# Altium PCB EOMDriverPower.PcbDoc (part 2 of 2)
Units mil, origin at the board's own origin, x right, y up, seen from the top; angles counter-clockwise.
Board outline 6400 x 9100 mil, 6 copper layers (Top Layer, GND1, PWR1, PWR2, GND2, Bottom Layer); 300 components, 184 nets, 876 pads, 174 vias.
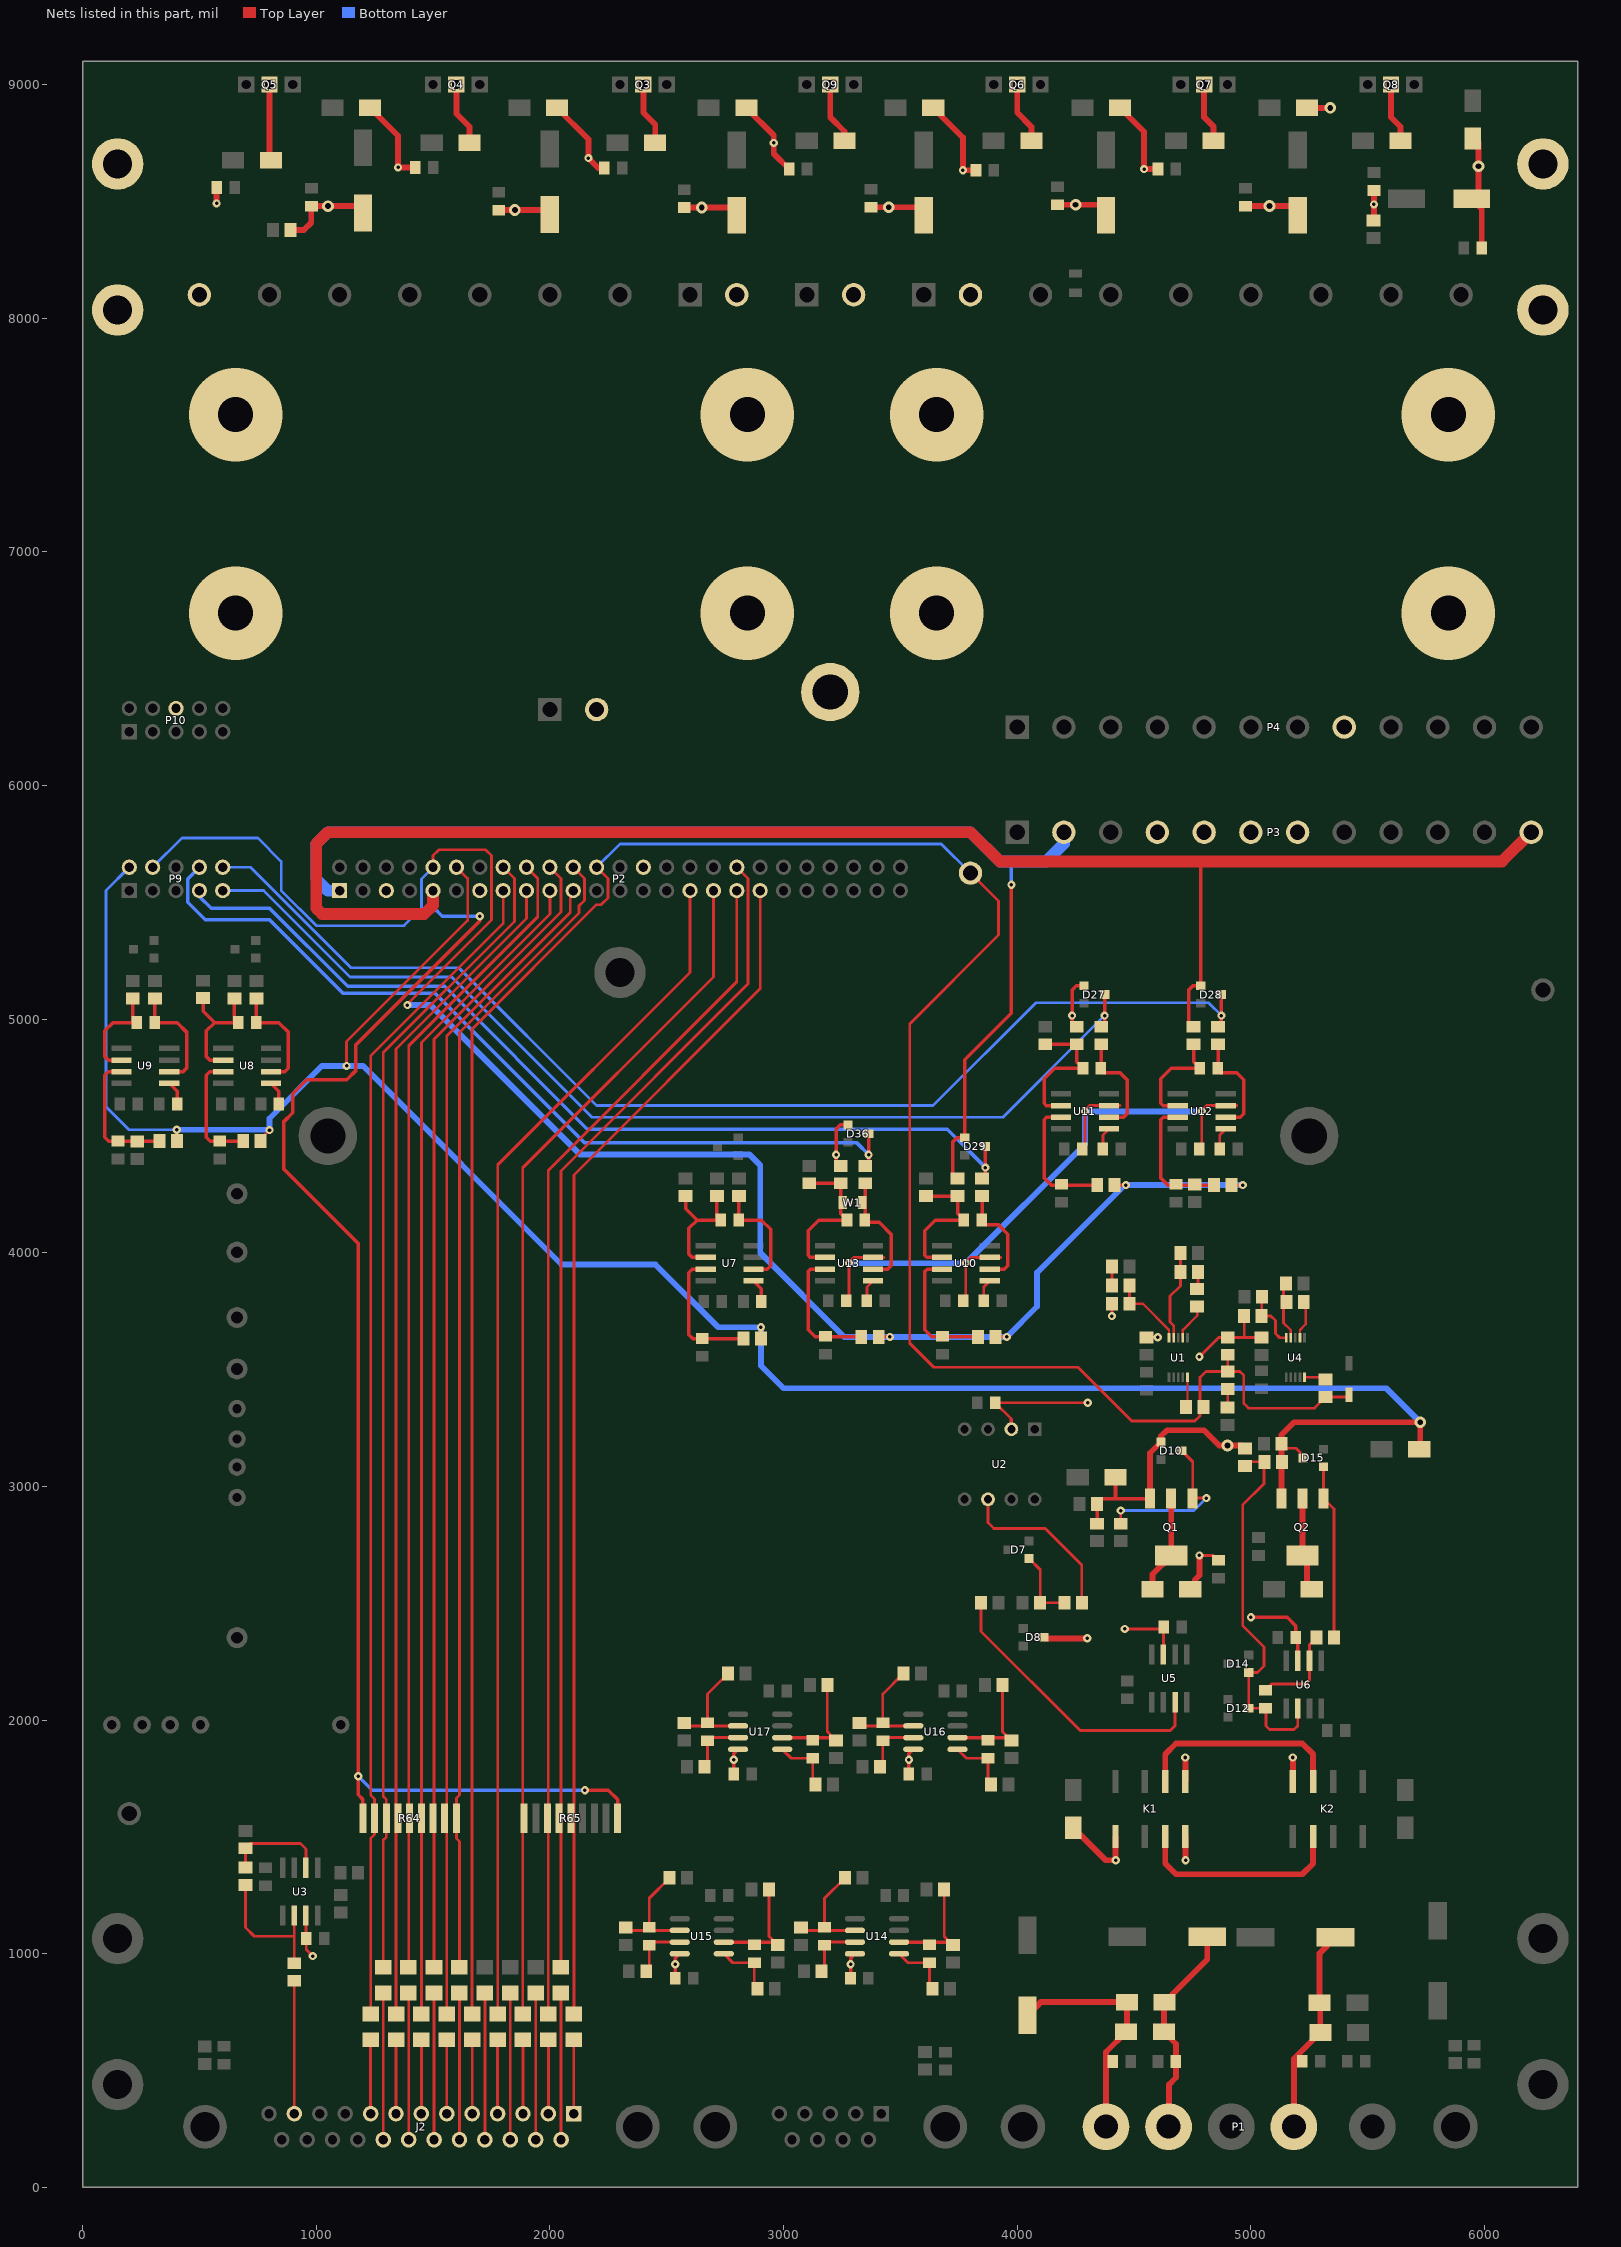
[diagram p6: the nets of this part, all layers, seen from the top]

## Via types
v1: diameter 35, hole 15, Top Layer to Bottom Layer, 147 vias
v2: diameter 50, hole 25, Top Layer to Bottom Layer, 19 vias
v3: diameter 280/400 (per signal layer), hole 150, Top Layer to Bottom Layer, 8 vias

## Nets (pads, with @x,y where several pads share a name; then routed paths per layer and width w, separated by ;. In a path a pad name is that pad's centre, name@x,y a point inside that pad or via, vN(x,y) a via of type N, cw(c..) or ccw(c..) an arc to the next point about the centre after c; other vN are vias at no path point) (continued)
NetC24_1: C24.1 R32.2 U6.6 | length 399.9
  Top Layer w12: C24.1@5063,2128.39 5089.61,2155 5235,2155 5251,2171 U6.6@5251,2254.36 5251,2323.4 R32.2@5280.6,2353
NetC24_2: C24.2 D12.3 D14.1 R29.2 R31.1 U6.2 | length 1640.3
  Top Layer w12: R29.2@4975,3087.6 4993,3105.6 5056.6,3105.6 5056.6,3011.6 4965,2920 4965,2405 5056.6,2313.4 5056.6,2231.6 5028.6,2203.6 D14.1@4991.29,2203.6 D12.3@4991.29,2051 5062.39,2051 C24.2@5063,2051.61 5065,2049.61 5065,1975 5080,1960 5185,1960 5201,1976 U6.2@5201,2049.64
NetC26_2: C26.2 R34.2 U7.3 | length 583.5
  Top Layer w15: U7.3@2666.64,3930 2610,3930 2595,3915 2595,3650 2612,3633 R34.2@2828.6,3633
NetC27_2: C27.2 R35.2 U8.3 | length 507.5
  Top Layer w15: U8.3@601.64,4775 545,4775 530,4760 530,4495 547,4478 R35.2@687.6,4478
NetC28_2: C28.2 R36.2 R39.1 U9.3 | length 583.5
  Top Layer w15: U9.3@166.64,4775 110,4775 95,4760 95,4495 112,4478 R36.2@328.6,4478
NetC32_2: C32.2 U7.5 | length 102.1
  Top Layer w15: U7.5@2871.36,3880 2905.39,3845.98 C32.2@2905.39,3792
NetC33_2: C33.2 U8.5 | length 102.1
  Top Layer w15: U8.5@806.36,4725 840.39,4690.98 C33.2@840.39,4637
NetC34_2: C34.2 U9.5 | length 102.1
  Top Layer w15: U9.5@371.36,4725 405.39,4690.98 C34.2@405.39,4637
NetC35_1: C35.1 R41.2 U7.6 | length 489
  Top Layer w15: R41.2@2808.39,4240.98 C35.1@2808.39,4140 2905,4140 2945,4100 2945,3945 2930,3930 U7.6@2871.36,3930
NetC35_2: C35.2 R37.2 R40.2 U7.2 | length 568.5
  Top Layer w15: R37.2@2581,4243.6 2581,4189 2630,4140 ; U7.2@2666.64,3980 2610,3980 2595,3995 2595,4105 2630,4140 ; R40.2@2715,4243.6 2715,4145 C35.2@2710,4140 ; C35.2@2731.61,4140 C35.2@2710,4140 ; 2630,4140 C35.2@2710,4140
NetC36_1: C36.1 R43.2 U8.6 | length 489
  Top Layer w15: R43.2@743.39,5085.98 C36.1@743.39,4985 840,4985 880,4945 880,4790 865,4775 U8.6@806.36,4775
NetC36_2: C36.2 R38.2 R42.2 U8.2 | length 569.5
  Top Layer w15: R38.2@516,5089.6 516,5034 565,4985 ; U8.2@601.64,4825 545,4825 530,4840 530,4950 565,4985 ; R42.2@650,5088.6 650,4990 C36.2@645,4985 ; C36.2@666.61,4985 C36.2@645,4985 ; 565,4985 C36.2@645,4985
NetC37_1: C37.1 R45.2 U9.6 | length 489
  Top Layer w15: R45.2@308.39,5085.98 C37.1@308.39,4985 405,4985 445,4945 445,4790 430,4775 U9.6@371.36,4775
NetC37_2: C37.2 R44.2 U9.2 | length 444.6
  Top Layer w15: U9.2@166.64,4825 110,4825 95,4840 95,4950 130,4985 C37.2@210,4985 ; R44.2@215,5088.6 215,4990 C37.2@210,4985 ; C37.2@231.61,4985 C37.2@210,4985
NetC41_1: C41.1 R47.2 U10.3 | length 566.8
  Top Layer w15: U10.3@3677.64,3930 3615,3930 3605,3920 3605,3670 3635,3640 R47.2@3832.6,3640
NetC42_1: C42.1 R48.2 U11.3 | length 566.8
  Top Layer w15: U11.3@4187.64,4580 4125,4580 4115,4570 4115,4320 4145,4290 R48.2@4342.6,4290
NetC43_1: C43.1 R49.2 R52.1 U12.3 | length 566.8
  Top Layer w15: U12.3@4687.64,4580 4625,4580 4615,4570 4615,4320 4645,4290 R49.2@4842.6,4290
NetC47_1: C47.1 U10.5 | length 100.7
  Top Layer w12: C47.1@3856.61,3790 3856.61,3854.25 U10.5@3882.36,3880
NetC48_1: C48.1 U11.5 | length 100.7
  Top Layer w12: C48.1@4366.61,4440 4366.61,4504.25 U11.5@4392.36,4530
NetC49_1: C49.1 U12.5 | length 100.7
  Top Layer w12: C49.1@4866.61,4440 4866.61,4504.25 U12.5@4892.36,4530
NetC50_1: C50.1 R50.2 R54.1 U10.2 | length 615.7
  Top Layer w15: R50.2@3610,4242.6 R54.1@3745,4242.6 3745,4166.61 C50.1@3771.61,4140 3650,4140 3605,4095 3605,3990 3615,3980 U10.2@3677.64,3980
NetC50_2: C50.2 R53.1 U10.6 | length 456.3
  Top Layer w15: R53.1@3850,4242.6 3850,4140 3870,4120 3920,4120 3960,4080 3960,3945 3945,3930 U10.6@3882.36,3930
NetC51_1: C51.1 R51.2 R56.1 U11.2 | length 615.7
  Top Layer w15: R51.2@4120,4892.6 R56.1@4255,4892.6 4255,4816.61 C51.1@4281.61,4790 4160,4790 4115,4745 4115,4640 4125,4630 U11.2@4187.64,4630
NetC51_2: C51.2 R55.1 U11.6 | length 468
  Top Layer w15: R55.1@4360,4892.6 4360,4780 4370,4770 4440,4770 4470,4740 4470,4595 4455,4580 U11.6@4392.36,4580
NetC52_1: C52.1 R58.1 U12.2 | length 480.7
  Top Layer w15: U12.2@4687.64,4630 4625,4630 4615,4640 4615,4745 4660,4790 C52.1@4781.61,4790 4755,4816.61 R58.1@4755,4892.6
NetC52_2: C52.2 R57.1 U12.6 | length 468
  Top Layer w15: R57.1@4860,4892.6 4860,4780 4870,4770 4940,4770 4970,4740 4970,4595 4955,4580 U12.6@4892.36,4580
NetC56_1: C56.1 R60.2 U13.3 | length 566.8
  Top Layer w15: U13.3@3177.64,3930 3115,3930 3105,3920 3105,3670 3135,3640 R60.2@3332.6,3640
NetC62_1: C62.1 U13.5 | length 100.7
  Top Layer w12: C62.1@3356.61,3790 3356.61,3854.25 U13.5@3382.36,3880
NetC63_1: C63.1 R61.2 R63.1 U13.2 W1.1 | length 712
  Top Layer w8: W1.1@3253.66,4215 W1.1@3295,4215
  Top Layer w15: R61.2@3110,4297.6 R63.1@3245,4297.6 3245,4166.61 C63.1@3271.61,4140 3150,4140 3105,4095 3105,3990 3115,3980 U13.2@3177.64,3980
NetC63_2: C63.2 R62.1 U13.6 W1.2 | length 505.4
  Top Layer w15: R62.1@3350,4297.6 3350,4150 3370,4130 3410,4130 3460,4080 3460,3945 3445,3930 U13.6@3382.36,3930
NetC79_1: C79.1 R72.2 U14.7 | length 252.9
  Top Layer w12: R72.2@3162.4,925 3175,937.6 C79.1@3175,1036.61 3188.39,1050 U14.7@3305.51,1050
NetC79_2: C79.2 R67.1 R73.2 U14.6 | length 483.5
  Top Layer w12: R73.2@3075,1112.4 3087.4,1100 U14.6@3305.51,1100 ; C79.2@3175,1113.39 3175,1237.4 R67.1@3262.6,1325
NetC80_1: C80.1 R76.2 U15.7 | length 252.9
  Top Layer w12: R76.2@2412.4,925 2425,937.6 C80.1@2425,1036.61 2438.39,1050 U15.7@2555.51,1050
NetC80_2: C80.2 R69.1 R77.2 U15.6 | length 483.5
  Top Layer w12: R77.2@2325,1112.4 2337.4,1100 U15.6@2555.51,1100 ; C80.2@2425,1113.39 2425,1237.4 R69.1@2512.6,1325
NetC81_1: C81.1 R71.2 U14.1 | length 263.2
  Top Layer w12: U14.1@3494.49,1000 3532.87,961.61 C81.1@3625,961.61 3625,862.6 R71.2@3637.6,850
NetC81_2: C81.2 R66.1 R70.2 U14.2 | length 471.1
  Top Layer w12: R66.1@3687.4,1275 3687.4,1075 3712.4,1050 R70.2@3725,1037.4
  Top Layer w15: U14.2@3494.49,1050 R70.2@3712.4,1050
NetC82_1: C82.1 R75.2 U15.1 | length 263.2
  Top Layer w12: U15.1@2744.49,1000 2782.87,961.61 C82.1@2875,961.61 2875,862.6 R75.2@2887.6,850
NetC82_2: C82.2 R68.1 R74.2 U15.2 | length 471.1
  Top Layer w12: R68.1@2937.4,1275 2937.4,1075 2962.4,1050 R74.2@2975,1037.4
  Top Layer w15: U15.2@2744.49,1050 R74.2@2962.4,1050
NetC87_1: C87.1 R84.2 U16.7 | length 252.9
  Top Layer w12: R84.2@3412.4,1800 3425,1812.6 C87.1@3425,1911.61 3438.39,1925 U16.7@3555.51,1925
NetC87_2: C87.2 R79.1 R85.2 U16.6 | length 483.5
  Top Layer w12: R85.2@3325,1987.4 3337.4,1975 U16.6@3555.51,1975 ; C87.2@3425,1988.39 3425,2112.4 R79.1@3512.6,2200
NetC88_1: C88.1 R88.2 U17.7 | length 252.9
  Top Layer w12: R88.2@2662.4,1800 2675,1812.6 C88.1@2675,1911.61 2688.39,1925 U17.7@2805.51,1925
NetC88_2: C88.2 R81.1 R89.2 U17.6 | length 483.5
  Top Layer w12: R89.2@2575,1987.4 2587.4,1975 U17.6@2805.51,1975 ; C88.2@2675,1988.39 2675,2112.4 R81.1@2762.6,2200
NetC89_1: C89.1 R83.2 U16.1 | length 263.2
  Top Layer w12: U16.1@3744.49,1875 3782.87,1836.61 C89.1@3875,1836.61 3875,1737.6 R83.2@3887.6,1725
NetC89_2: C89.2 R78.1 R82.2 U16.2 | length 471.1
  Top Layer w12: R78.1@3937.4,2150 3937.4,1950 3962.4,1925 R82.2@3975,1912.4
  Top Layer w15: U16.2@3744.49,1925 R82.2@3962.4,1925
NetC90_1: C90.1 R87.2 U17.1 | length 263.2
  Top Layer w12: U17.1@2994.49,1875 3032.87,1836.61 C90.1@3125,1836.61 3125,1737.6 R87.2@3137.6,1725
NetC90_2: C90.2 R80.1 R86.2 U17.2 | length 471.1
  Top Layer w12: R80.1@3187.4,2150 3187.4,1950 3212.4,1925 R86.2@3225,1912.4
  Top Layer w15: U17.2@2994.49,1925 R86.2@3212.4,1925
NetD7_1: D7.1 R18.2 R20.1 | length 312.7
  Top Layer w12: D7.1@4050.29,2691.6 4098.4,2643.49 R20.1@4098.4,2502 R18.2@4201.6,2502
NetD10_3: D10.3 Q1.1 R27.2 | length 726.6
  Top Layer w12: R27.2@4443,2840.4 v1(4443,2897) ; D10.3@4704.29,3153 4751.5,3105.79 4751.5,2950 v1(4810,2950)
  Bottom Layer w12: v1(4443,2897) 4757,2897 v1(4810,2950)
NetD11_2: D11.2 Q1.2 Q1.4 | length 421.1
  Top Layer w25: D11.2@4579.29,2560 4579.29,2624.24 Q1.4@4659,2703.95 Q1.2@4659,2948.05
NetD15_1: D15.1 Q2.1 R32.1 | length 749.9
  Top Layer w12: D15.1@5311.29,3084.6 5311.29,2948.31 Q2.1@5311.55,2948.05 5355.4,2904.2 R32.1@5355.4,2353
NetD17_1: D17.1 Q2.2 Q2.4 | length 404.5
  Top Layer w25: Q2.2@5221,2948.05 Q2.4@5221,2703.95 5240,2684.95 5240,2580.71 D17.1@5260.71,2560
NetD22_1: D22.1 Q3.2 | length 271
  Top Layer w25: Q3.2@2400,9000 2400,8880 2450.71,8829.29 D22.1@2450.71,8750
NetD23_1: D23.1 Q4.2 | length 273.1
  Top Layer w25: Q4.2@1600,9000 1600,8875 1655.71,8819.29 D23.1@1655.71,8750
NetD24_1: D24.1 Q5.2 | length 327.4
  Top Layer w25: Q5.2@800,9000 800,8680.71 D24.1@805.71,8675
NetD31_2: D31.2 Q6.2 | length 265.1
  Top Layer w25: Q6.2@4000,9000 4000,8880 4060.71,8819.29 D31.2@4060.71,8760
NetD32_2: D32.2 Q7.2 | length 256.9
  Top Layer w25: Q7.2@4800,9000 4800,8860 4840.71,8819.29 D32.2@4840.71,8760
NetD33_2: D33.2 Q8.2 | length 256.9
  Top Layer w25: Q8.2@5600,9000 5600,8860 5640.71,8819.29 D33.2@5640.71,8760
NetD37_2: D37.2 Q9.2 | length 265.1
  Top Layer w25: Q9.2@3200,9000 3200,8860 3260.71,8799.29 D37.2@3260.71,8760
NetFR1_2: FR1.2 J2.1 | length 315.6
  Top Layer w12: J2.1@2102.2,315.91 FR1.2@2102.2,631.48
NetFR2_2: FR2.2 J2.14 | length 627.8
  Top Layer w12: J2.14@2047.85,204.09 FR2.2@2047.85,831.88
NetFR3_2: FR3.2 J2.2 | length 315.6
  Top Layer w12: J2.2@1993.5,315.91 FR3.2@1993.5,631.48
NetFR4_2: FR4.2 J2.15 | length 627.8
  Top Layer w12: J2.15@1939.15,204.09 FR4.2@1939.15,831.88
NetFR5_2: FR5.2 J2.3 | length 315.6
  Top Layer w12: J2.3@1884.8,315.91 FR5.2@1884.8,631.48
NetFR6_2: FR6.2 J2.16 | length 627.8
  Top Layer w12: J2.16@1830.45,204.09 FR6.2@1830.45,831.88
NetFR7_2: FR7.2 J2.4 | length 315.6
  Top Layer w12: J2.4@1776.1,315.91 FR7.2@1776.1,631.48
NetFR8_2: FR8.2 J2.17 | length 627.8
  Top Layer w12: J2.17@1721.75,204.09 FR8.2@1721.75,831.88
NetFR9_2: FR9.2 J2.5 | length 315.6
  Top Layer w12: J2.5@1667.4,315.91 FR9.2@1667.4,631.48
NetFR10_2: FR10.2 J2.18 | length 627.8
  Top Layer w12: J2.18@1613.05,204.09 FR10.2@1613.05,831.88
NetFR11_2: FR11.2 J2.6 | length 315.6
  Top Layer w12: J2.6@1558.7,315.91 FR11.2@1558.7,631.48
NetFR12_2: FR12.2 J2.19 | length 627.8
  Top Layer w12: J2.19@1504.35,204.09 FR12.2@1504.35,831.88
NetFR13_2: FR13.2 J2.7 | length 315.6
  Top Layer w12: J2.7@1450,315.91 FR13.2@1450,631.48
NetFR14_2: FR14.2 J2.20 | length 627.8
  Top Layer w12: J2.20@1395.65,204.09 FR14.2@1395.65,831.88
NetFR15_2: FR15.2 J2.8 | length 315.6
  Top Layer w12: J2.8@1341.3,315.91 FR15.2@1341.3,631.48
NetFR16_2: FR16.2 J2.21 | length 627.8
  Top Layer w12: J2.21@1286.95,204.09 FR16.2@1286.95,831.88
NetFR17_2: FR17.2 J2.9 | length 316.1
  Top Layer w12: J2.9@1232.6,315.91 1232.6,631.48 FR17.2@1233,631.88
NetK1_1: K1.1 K2.4 | length 902.4
  Top Layer w25: K1.1@4633.39,1501.89 4633.39,1386.61 4680,1340 5220,1340 5266.61,1386.61 K2.4@5266.61,1501.89
NetK1_4: K1.4 K2.1 | length 902.4
  Top Layer w25: K1.4@4633.39,1738.11 4633.39,1853.39 4680,1900 5220,1900 5266.61,1853.39 K2.1@5266.61,1738.11
NetR4_2: R4.2 R6T.2 U1.10 | length 327.7
  Top Layer w10: R4.2@4480.4,3782 4538,3782 4650,3670 U1.10@4650,3636.29
  Top Layer w12: R4.2@4480.4,3782 R6T.2@4480.4,3860
NetR5_1: R5.1 R7T.2 U1.9 | length 388.4
  Top Layer w10: 4668.69,3689.31 4669.69,3688.31 U1.9@4669.69,3636.29
  Top Layer w12: 4668.69,3688.31 4668.69,3689.31 4654.34,3703.66 4654.34,3814.34 4698.6,3858.6 R7T.2@4698.6,3918 R5.1@4698.6,3999
NetR6_2: R6.2 R6T.1 | length 81
  Top Layer w12: R6T.1@4405.6,3860 R6.2@4405.6,3941
NetR7_1: R7.1 U1.7 | length 158.6
  Top Layer w10: U1.7@4709.06,3636.29 4709.06,3670.06 4770,3731 R7.1@4770,3769.6
NetR7_2: R7.2 R7T.1 | length 75
  Top Layer w12: R7.2@4770,3844.4 4773.4,3847.8 R7T.1@4773.4,3918
NetR10_2: R10.2 R15.1 U3.2 | length 441.2
  Top Layer w12: R15.1@697,1368.4 R10.2@697,1451.6 717.9,1472.5 932.5,1472.5 956,1449 U3.2@956,1368.36
NetR11_1: R11.1 U1.5 | length 129.5
  Top Layer w10: R11.1@4728.74,3346.14 U1.5@4728.74,3467
  Top Layer w11.5: R11.1@4722.6,3340 R11.1@4728.74,3346.14
NetR13_1: R13.1 R16.2 U4.10 | length 268.9
  Top Layer w10: 5123.71,3636.29 U4.10@5151,3636.29
  Top Layer w11: R13.1@5046.4,3730 R13.1@5057.29,3730
  Top Layer w12: R16.2@5047.4,3812 5046.4,3811 R13.1@5046.4,3730 5085,3730 5105,3710 5105,3655 5123.71,3636.29
NetR14_1: R14.1 R17.2 U4.9 | length 249.8
  Top Layer w10: 5140,3700 5170.69,3669.31 U4.9@5170.69,3636.29 ; R14.1@5140,3858.4 R14.1@5150.6,3869
  Top Layer w12: 5140,3700 R14.1@5140,3858.4
NetR15_2: R15.2 R19.2 U3.6 | length 609.6
  Top Layer w12: R15.2@697,1293.6 697,1113 735,1075 906,1075 ; R19.2@906,959.4 906,1075 ; U3.6@906,1163.64 906,1075
NetR17_1: R17.1 U4.7 | length 166.6
  Top Layer w10: U4.7@5210.06,3636.29 5210.06,3670.06 5235,3695
  Top Layer w12: R17.1@5226.4,3789 5235,3780.4 5235,3695
NetR18_1: R18.1 U2.6 | length 738.1
  Top Layer w12: U2.6@3875,2945 3875,2845 3900,2820 4120,2820 4276.4,2663.6 R18.1@4276.4,2502
NetR22_2: R22.2 U5.3 | length 1238.1
  Top Layer w12: R22.2@3845.6,2502 3845.6,2379.4 4270,1955 4655,1955 4676,1976 U5.3@4676,2076.64
NetR23_1: R23.1 U4.5 | length 94.2
  Top Layer w10: U4.5@5229.74,3467 5310.4,3467 R23.1@5320,3457.4
NetR25_1: R25.1 R26.2 | length 80.2
  Top Layer w12: R26.2@4901,3337.4 R25.1@4901,3417.6
NN18: C4.1 C9.2 D2.2 D4.2 K1.3 P1.4 | length 1002.3
  Top Layer w25: v1@4720,1400 K1.3@4720,1501.89 ; P1.4@5220,260 5185,295 5185,550.71 D2.2@5297.29,663 5297.29,787 D4.2@5294.29,790 5294.29,1002.03 C9.2@5362.26,1070
  other v1: 4720.79,1400
OK: D9.2 FR9.1 P2.24 R11.2 R23.2 R24.1 R25.2 TP8.1 | length 11525.8
  Top Layer w12: FR9.1@1667,742.12 1667,4957 2200,5490 2220,5490 2248.16,5518.16 2248.16,5601.84 P2.24@2200,5650 ; TP8.1@3800,5625 3920,5505 3920,5360 3540,4980 3540,3613.08 3643.08,3510 4260,3510 4490,3280 4760,3280 4782,3302 4782,3467 4807.4,3492.4 R25.2@4901,3492.4 ; R24.1@4901,3563.6 R25.2@4901,3492.4 ; D9.2@5420,3393.07 5409.53,3382.6 R23.2@5320,3382.6 5272.4,3335 4990,3335 4970,3355 4970,3475 4952.6,3492.4 R25.2@4901,3492.4
  Bottom Layer w12: P2.24@2200,5650 2300,5750 3675,5750 TP8.1@3800,5625
P5: D28.1 P2.9 P3.12 R58.2 R64.1 R65.1 | length 12914.8
  Top Layer w15: R64.1@1200,1580 1200,1660 1180,1680 v1(1180,1760) 1180,4040 860,4360 860,4560 900,4600 900,4680 960,4740 1130,4740 1170,4780 1170,4890 1700,5420 v1(1700,5440) ; v1(2150,1700) 2250,1700 2290,1660 R65.1@2290,1580 ; R58.2@4755,4967.4 4735,4987.4 4735,5125 4752.4,5142.4 D28.1@4785.71,5142.4 4785.71,5664.29 4775,5675
  Top Layer w50: P2.9@1500,5550 1500,5487.5 1462.5,5450 1025,5450 1000,5475 1000,5750 1050,5800 3800,5800 3925,5675 4775,5675 6075,5675 P3.12@6200,5800
  Bottom Layer w15: v1(1180,1760) 1240,1700 v1(2150,1700) ; P2.9@1500,5550 1500,5480 1540,5440 v1(1700,5440)
P5C: D28.3 P9.10 R57.2 | length 5045.3
  Top Layer w15: R57.2@4860,4967.4 4874.29,4981.69 v1(4874.29,5015) D28.3@4874.29,5105
  Bottom Layer w12: P9.10@600,5650 719.34,5650 1149.34,5220 1610,5220 2200,4630 3640,4630 4080,5070 4819.29,5070 v1(4874.29,5015)
P15: C15.2 C76.1 C78.1 C84.1 C86.1 D27.1 P2.5 P3.4 R56.2 U3.7 U14.8 U15.8 U16.8 U17.8 | length 838.5
  Top Layer w12: C15.2@956,1066.61 U3.7@956,1163.64 ; C15.2@957.61,1065 957.61,1017.39 v1(985,990)
  Top Layer w15: C78.1@2536.61,900 2536.61,981.1 U15.8@2555.51,1000 ; C86.1@2786.61,1775 2786.61,1856.1 U17.8@2805.51,1875 ; C76.1@3286.61,900 3286.61,981.1 U14.8@3305.51,1000 ; C84.1@3536.61,1775 3536.61,1856.1 U16.8@3555.51,1875 ; R56.2@4255,4967.4 4235,4987.4 4235,5125 4252.4,5142.4 D27.1@4285.71,5142.4
  other v1: 2536.61,955 3286.61,955 2786.61,1830 3536.61,1830 4235,5015
P15C: D27.3 P9.9 R55.2 | length 4499.8
  Top Layer w15: R55.2@4360,4967.4 4374.29,4981.69 v1(4374.29,5015) D27.3@4374.29,5105
  Bottom Layer w12: P9.9@600,5550 775,5550 1145,5180 1580,5180 2180,4580 3939.29,4580 v1(4374.29,5015)
P18: C21.1 D11.1 K1.6 P3.7 R9.2 R13.2 R21.2 R24.2 | length 805.9
  Top Layer w11: R9.2@4553,3638.4 R9.2@4560.6,3646
  Top Layer w12: R9.2@4553,3638.4 v1(4601.6,3638.4) ; v1(4780,2705) 4839.39,2705 C21.1@4861,2683.39 ; v1(4780,3555) 4780.2,3555 4862.6,3637.4 4970,3637.4 ; R13.2@4971.6,3730 4971.6,3639 4970,3637.4 ; R21.2@5046,3637.4 4970,3637.4
  Top Layer w25: K1.6@4720,1738.11 v1@4720,1840 ; D11.1@4740.71,2560 4760,2579.29 4760,2600 4780,2620 v1(4780,2705)
  other v1: 4719.21,1840
P21: D29.1 P2.1 P3.2 R54.2 | length 5113.2
  Top Layer w15: R54.2@3745,4317.4 3725,4337.4 3725,4475 3742.4,4492.4 D29.1@3775.71,4492.4 3775.71,4825.71 3975,5025 v1(3975,5575)
  Bottom Layer w15: v1(3975,5575) 3975,5675
  Bottom Layer w50: P2.1@1100,5550 1050,5550 1000,5600 1000,5750 1050,5800 3800,5800 3925,5675 3975,5675 4125,5675 4200,5750 P3.2@4200,5800
P21C: D29.3 P9.7 R53.2 | length 4013.3
  Top Layer w15: R53.2@3850,4317.4 3864.29,4331.69 v1(3864.29,4365) D29.3@3864.29,4455
  Bottom Layer w15: P9.7@500,5550 500,5525 550,5475 800,5475 1135,5140 1550,5140 2160.71,4529.29 3700,4529.29 v1(3864.29,4365)
P24: C2.2 C7.1 C14.2 C19.2 C44.1 C45.1 C46.1 C59.1 D1.2 D3.2 D5.2 D8.3 K1.7 P1.1 P3.6 R4.1 U2.2 U5.7 U10.7 U11.7 U12.7 U13.7 | length 5618.3
  Top Layer w12: C59.1@3268.39,3790 3280,3801.61 v1(3280,3955) 3280,3960 3300,3980 U13.7@3382.36,3980 3430,3980 ; C44.1@3768.39,3790 3780,3801.61 v1(3780,3955) ; v1@3780,3960 3800,3980 U10.7@3882.36,3980 3930,3980 ; 3975,3288.39 C14.2@3905.39,3358 v1(4302,3358) ; C45.1@4278.39,4440 4290,4451.61 v1(4290,4605) ; v1@4290,4610 4310,4630 U11.7@4392.36,4630 4440,4630 ; v1(4405.6,3729.4) R4.1@4405.6,3782 ; v1(4460,2390) C19.2@4625,2390 ; U5.7@4626,2281.36 C19.2@4626,2400 ; C46.1@4778.39,4440 4790,4451.61 v1(4790,4605) 4790,4610 4810,4630 U12.7@4892.36,4630 4940,4630
  Top Layer w15: U2.2@3975,3245 3975,3288.39 ; v1@4420.79,1400 v1(4421.57,1400)
  Top Layer w25: C7.1@4044,736.74 4100.26,793 D3.2@4469.29,793 4469.29,669 D1.2@4466.29,666 4380,579.71 4380,290 P1.1@4410,260 ; D8.3@4114.29,2355 4119.29,2350 v1(4300,2350) ; D5.2@4240,1539.29 4379.29,1400 4420.79,1400 K1.7@4420.79,1501.89
  Bottom Layer w25: v1(3280,3955) v1(3780,3955) 4290,4465 v1(4290,4605) v1(4790,4605)
P24A: D36.3 P9.8 R62.2 | length 3676.2
  Top Layer w15: R62.2@3350,4372.4 3364.29,4386.69 v1(3364.29,4420) D36.3@3364.29,4510
  Bottom Layer w15: P9.8@500,5650 449.66,5599.66 449.66,5500.34 525,5425 800,5425 1115,5110 1510,5110 2150,4470 3314.29,4470 v1(3364.29,4420)
P24AMP: D36.1 P3.5 R63.2 | length 223.8
  Top Layer w15: R63.2@3245,4372.4 3225,4392.4 v1(3225,4420) 3225,4530 3242.4,4547.4 D36.1@3275.71,4547.4
PGND: B1.1 B1.2 B3.1 B3.2 C38.2 C39.2 C40.2 C53.2 C54.2 C55.2 C57.2 C58.1 C60.1 C61.2 C64.2 C65.1 C66.1 C67.2 C68.2 C69.1 C70.1 C71.2 C72.1 C73.2 C74.2 D21.2 D25.2 D26.2 D30.1 D34.1 D35.1 D38.1 P4.8 P5.2 P6.2 P7.2 P8.2 P10.6 pad.0@3200,6400 R46.1 R59.2 TP1.1 | length 4148.4
  Top Layer w25: v1(573.61,8491.39) C40.2@573.61,8559 ; R46.1@889.4,8378 948,8378 979,8409 C57.2@979,8479.61 v2(1050,8479.61) 1183.62,8479.61 C60.1@1203,8460.24 ; D21.2@1230.71,8900 1350,8780.71 v1(1350,8645) C39.2@1423.61,8645 ; C64.2@1781,8462.61 1981.62,8462.61 C66.1@2000,8444.24 ; D26.2@2030.71,8900 2165,8765.71 v1(2165,8685) 2207,8643 C38.2@2232.61,8643 ; C68.2@2575,8473.61 2784.62,8473.61 C72.1@2800,8458.24 ; D25.2@2840.71,8900 2958,8782.71 2958,8703.61 C71.2@3023.61,8638 ; C70.1@3374,8474.61 3587.62,8474.61 C74.2@3600,8462.24 ; D38.1@3640.71,8900 3768,8772.71 v1(3768,8633) C53.2@3823.61,8633 ; C69.1@4172,8485.61 4379.62,8485.61 C73.2@4397,8468.24 ; D34.1@4440.71,8900 4543,8797.71 v1(4543,8638) C54.2@4602.61,8638 ; C65.1@4977,8479.61 5186.62,8479.61 C67.2@5203,8463.24 ; D35.1@5240.71,8900 v2(5340,8900) ; R59.2@5525,8418.4 5527,8420.4 v1(5527,8487) C55.2@5527,8546.61 ; D30.1@5974.39,8753 v2(5974.39,8650) 5974.39,8539.62 C61.2@5945.76,8511 5988.39,8468.38 C58.1@5988.39,8300
  other v1: 2958,8750
  other v2: 1850,8462.61 2650,8473.61 3450,8474.61 5080,8480 4250,8485.61
  other v3: 655,6738 2845,6738 3655,6738 5845,6738 655,7587 2845,7587 3655,7587 5845,7587
POL: P2.28
PP18: C3.2 C8.1 D1.1 D3.1 K2.3 P1.2 | length 1027.9
  Top Layer w25: P1.2@4645,260 4650,265 4650,440 4680,470 4680,613.71 D1.1@4627.71,666 4627.71,790 D3.1@4630.71,793 4813.26,975.55 C8.1@4813.26,1073 ; K2.3@5180,1738.11 v1@5180,1840
  other v1: 5179.21,1840
RF_ON: FR7.1 P2.31 | length 5148.8
  Top Layer w12: FR7.1@1777,742.12 1777,4377 2600,5200 P2.31@2600,5550
SLOWCTRL: J2.12 R19.1 | length 568.7
  Top Layer w12: J2.12@906,315.91 R19.1@906,884.6
SP0: FR1.1 P2.37 R65.5 | length 5138
  Top Layer w12: FR1.1@2103,742.12 2103,4333 2900,5130 P2.37@2900,5550
SP1: FR2.1 P2.36 R65.6 | length 5059.7
  Top Layer w12: FR2.1@2047,942.12 2047,4350.31 2848.16,5151.47 2848.16,5601.84 P2.36@2800,5650
SP2: FR3.1 P2.35 R65.7 | length 5142.2
  Top Layer w12: FR3.1@1993,742.12 1993,4353 2800,5160 P2.35@2800,5550
VAL0: FR10.1 P2.22 R64.9 | length 4960.3
  Top Layer w12: FR10.1@1613,942.12 1613,1480 1600,1493 R64.9@1600,1580 1600,1667 1613,1680 1613,4943 2125.08,5455.08 2125.08,5485.08 2148.16,5508.16 2148.16,5601.84 P2.22@2100,5650
VAL1: FR11.1 P2.21 R64.8 | length 5032
  Top Layer w12: FR11.1@1559,742.12 1559,4929 2087.09,5457.09 2087.09,5537.09 P2.21@2100,5550
VAL2: FR12.1 P2.20 R64.7 | length 4953.2
  Top Layer w12: FR12.1@1504,942.12 1504,4914 2048.16,5458.16 2048.16,5601.84 P2.20@2000,5650
VAL3: FR13.1 P2.19 R64.6 | length 5035.7
  Top Layer w12: FR13.1@1450,742.12 R64.6@1450,1580 1450,4900 2000,5450 P2.19@2000,5550
VAL4: FR14.1 P2.18 R64.5 | length 4956.5
  Top Layer w12: FR14.1@1396,942.12 1396,4886 1948.16,5438.16 1948.16,5601.84 P2.18@1900,5650
VAL5: FR15.1 P2.17 R64.4 | length 5039
  Top Layer w12: FR15.1@1342,742.12 1342,4872.66 1900,5430.66 P2.17@1900,5550
VAL6: FR16.1 P2.16 R64.3 | length 4971
  Top Layer w12: FR16.1@1287,942.12 1287,1487 1300,1500 1300,1660 1287,1673 1287,4857 1848.16,5418.16 1848.16,5601.84 P2.16@1800,5650
VAL7: FR17.1 P2.15 R64.2 | length 5056.8
  Top Layer w12: FR17.1@1233,742.12 1233,1493 1250,1510 R64.2@1250,1580 1250,1663 1233,1680 1233,4843 1800,5410 P2.15@1800,5550
VALEN: FR5.1 P2.33 R65.9 | length 5145.9
  Top Layer w12: FR5.1@1884,742.12 1884,4364 2700,5180 P2.33@2700,5550
VDD: P2.13
VREFN: D15.3 D16.1 P2.12 P9.2 Q2.3 R31.2 R33.1 R34.1 R35.1 R36.1 | length 9983.4
  Top Layer w12: R36.1@403.4,4478 v1(403.4,4526.6) ; R35.1@762.4,4478 753,4478 v1(800,4525) ; v1(1130,4800) 1130,4904.55 1648.16,5422.71 1648.16,5601.84 P2.12@1600,5650 ; R34.1@2903.4,3633 v1(2903.4,3681.6) ; 5130.45,3074.05 R31.2@5132,3075.6 ; R33.1@5132,3163.6 5193.31,3163.6 5222.71,3134.2 D15.3@5222.71,3122
  Top Layer w25: Q2.3@5130.45,2948.05 5130.45,3220.45 5185,3275 v2(5725,3275) 5725,3164.29 D16.1@5720.71,3160
  Bottom Layer w12: P9.2@200,5650 100,5550 100,4625 198.4,4526.6 v1(403.4,4526.6)
  Bottom Layer w25: v1(403.4,4526.6) 800,4526.6 800,4575 1025,4800 1200,4800 2049.68,3950.32 2451.28,3950.32 2720,3681.6 v1(2903.4,3681.6) 2903.4,3516.6 3000,3420 5580,3420 v2(5725,3275)
VREFP: C22.1 D10.1 D13.2 P2.10 P9.4 Q1.3 R28.2 R29.1 R30.1 R47.1 R48.1 R49.1 R60.1 U6.7 | length 9157.1
  Top Layer w12: v1(1390,5060) 1390,5065 1750,5425 1750,5700 1725,5725 1525,5725 1500,5700 P2.10@1500,5650 ; R30.1@4342,2924.4 R30.1@4341.4,2925 R30.1@4364.45,2948.05 ; 4420,2948.05 4420.71,2948.76
  Top Layer w15: R60.1@3407.4,3640 v1(3455,3640) ; R47.1@3907.4,3640 v1(3955,3640) ; R28.2@4342,2840.4 R30.1@4342,2924.4 ; R30.1@4364.45,2948.05 4420,2948.05 Q1.3@4568.45,2948.05 ; R48.1@4417.4,4290 v1(4465,4290) ; 4420.71,2948.76 D13.2@4420.71,3040 ; R49.1@4917.4,4290 v1(4965,4290) ; v1(5000,2440) 5155,2440 5192.39,2402.61 C22.1@5192.39,2353 5201,2344.39 U6.7@5201,2254.36
  Top Layer w25: Q1.3@4568.45,2948.05 4568.45,3143.14 D10.1@4615.71,3190.4 4615.71,3215.71 4640.71,3240.71 4799.29,3240.71 4865,3175 v2(4900,3175) 4962.4,3175 R29.1@4975,3162.4
  Bottom Layer w12: P9.4@300,5650 425,5775 750,5775 850,5675 850,5550 1000,5400 1375,5400 1450,5475 1450,5600 P2.10@1500,5650
  Bottom Layer w25: v1(1390,5060) 1490,5060 2130,4420 2855,4420 2900,4375 2900,4000 3260,3640 v1(3455,3640) v1(3955,3640) 4085,3770 4085,3915 4460,4290 v1(4465,4290) v1(4965,4290)
pads on no net: D7.2 D8.2 D10.2 D12.2 D14.2 D15.2 D18.2 D19.2 D20.2 D27.2 D28.2 D29.2 D36.2 J1.5 K1.2 K1.5 K2.2 K2.5 R65.2 R65.3 R65.4 U1.1 U1.3 U1.4 U2.1 U2.3 U2.5 U2.7 U2.8 U3.1 U3.5 U3.8 U4.1 U4.3 U4.4 U5.1 U5.5 U5.8 U6.1 U6.5 U6.8 U7.1 U7.8 U8.1 U8.8 U9.1 U9.8 U10.1 U10.8 U11.1 U11.8 U12.1 U12.8 U13.1 U13.8

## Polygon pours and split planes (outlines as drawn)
PGND on GND1 (split plane): 6379.9,6125.08 20.1,6125.08 20.1,9079.9 6379.9,9079.9
GND on GND1 (split plane): 6379.9,20.1 20.1,20.1 20.1,5974.92 6379.9,5974.92
+24 on PWR1 (split plane): 4237.44,8275 4237.44,7862.56 4005.2,7862.56 3962.56,7905.2 3962.56,8150 3962.32,8152.45 3961.6,8154.81 3960.44,8156.98 3958.88,8158.88 3858.88,8258.88 3856.98,8260.44 3854.81,8261.6 3852.45,8262.32 3850,8262.56 2812.56,8262.56 2812.56,9079.9 4237.44,9079.9
-24 on PWR1 (split plane): 2787.44,8262.56 2550,8262.56 2547.55,8262.32 2545.19,8261.6 2543.02,8260.44 2541.12,8258.88 2441.12,8158.88 2439.56,8156.98 2438.4,8154.81 2437.68,8152.45 2437.44,8150 2437.44,7905.2 2394.8,7862.56 2162.56,7862.56 2162.56,9079.9 2787.44,9079.9
+18 on PWR1 (split plane): 6379.9,8262.56 4650,8262.56 4647.55,8262.32 4645.19,8261.6 4643.02,8260.44 4641.12,8258.88 4541.12,8158.88 4539.56,8156.98 4538.4,8154.81 4537.68,8152.45 4537.44,8150 4537.44,7905.2 4494.8,7862.56 4262.56,7862.56 4262.56,8275 4262.56,9079.9 6379.9,9079.9
+15 on PWR1 (split plane): 6379.9,6125.08 20.1,6125.08 20.1,8237.44 1744.8,8237.44 1837.44,8144.8 1837.44,7900 1837.68,7897.55 1838.4,7895.19 1839.56,7893.02 1841.12,7891.12 1891.12,7841.12 1893.02,7839.56 1895.19,7838.4 1897.55,7837.68 1900,7837.44 2400,7837.44 2402.45,7837.68 2404.81,7838.4 2406.98,7839.56 2408.88,7841.12 2458.88,7891.12 2460.44,7893.02 2461.6,7895.19 2462.32,7897.55 2462.56,7900 2462.56,8144.8 2555.2,8237.44 3844.8,8237.44 3937.44,8144.8 3937.44,7900 3937.68,7897.55 3938.4,7895.19 3939.56,7893.02 3941.12,7891.12 3991.12,7841.12 3993.02,7839.56 3995.19,7838.4 3997.55,7837.68 4000,7837.44 4500,7837.44 4502.45,7837.68 4504.81,7838.4 4506.98,7839.56 4508.88,7841.12 4558.88,7891.12 4560.44,7893.02 4561.6,7895.19 4562.32,7897.55 4562.56,7900 4562.56,8144.8 4655.2,8237.44 6379.9,8237.44
-18 on PWR1 (split plane): 2137.44,7862.56 1905.2,7862.56 1862.56,7905.2 1862.56,8150 1862.32,8152.45 1861.6,8154.81 1860.44,8156.98 1858.88,8158.88 1758.88,8258.88 1756.98,8260.44 1754.81,8261.6 1752.45,8262.32 1750,8262.56 20.1,8262.56 20.1,9079.9 2137.44,9079.9
P15 on PWR1 (split plane): 6379.9,20.1 20.1,20.1 20.1,5974.92 6379.9,5974.92
+5 on PWR2 (split plane): 6379.9,6125.08 6112.56,6125.08 6112.56,7660 6112.32,7662.45 6111.6,7664.81 6110.44,7666.98 6108.88,7668.88 5687.56,8090.2 5687.56,8825 5687.32,8827.45 5686.6,8829.81 5685.44,8831.98 5683.88,8833.88 5512.56,9005.2 5512.56,9079.9 6379.9,9079.9
no net on PWR2 (split plane): 5487.44,7044.8 5487.44,6125.08 5312.56,6125.08 5312.56,7219.68
P5 on PWR2 (split plane): 5487.44,5355.2 5291.12,5158.88 5044.8,4912.56 4862.56,4912.56 4862.56,4994.8 5308.88,5441.12 5310.44,5443.02 5311.6,5445.19 5312.32,5447.55 5312.56,5450 5312.56,5974.92 5487.44,5974.92
P18 on PWR2 (split plane): 5287.44,5455.2 4841.12,5008.88 4839.56,5006.98 4838.4,5004.81 4837.68,5002.45 4837.44,5000 4837.44,1772.56 4527.56,1772.56 4527.56,4959.8 5108.88,5541.12 5110.44,5543.02 5111.6,5545.19 5112.32,5547.55 5112.56,5550 5112.56,5974.92 5287.44,5974.92
VREFP on PWR2 (split plane): 5037.44,1912.56 4990,1912.56 4987.55,1912.32 4985.19,1911.6 4983.02,1910.44 4981.12,1908.88 4862.56,1790.32 4862.56,4887.44 5037.44,4887.44
N24 on PWR2 (split plane): 5887.44,5255.2 5641.12,5008.88 5639.56,5006.98 5638.4,5004.81 5637.68,5002.45 5637.44,5000 5637.44,112.56 5362.56,112.56 5362.56,4944.8 5521.44,5103.68 5708.88,5291.12 5710.44,5293.02 5711.6,5295.19 5712.32,5297.55 5712.56,5300 5712.56,5974.92 5887.44,5974.92
N18 on PWR2 (split plane): 5687.44,5305.2 5503.68,5121.44 5341.12,4958.88 5339.56,4956.98 5338.4,4954.81 5337.68,4952.45 5337.44,4950 5337.44,1352.56 5165.2,1352.56 5132.56,1385.2 5132.56,1474.8 5248.88,1591.12 5250.44,1593.02 5251.6,1595.19 5252.32,1597.55 5252.56,1600 5252.56,1860 5252.32,1862.45 5251.6,1864.81 5250.44,1866.98 5248.88,1868.88 5208.88,1908.88 5206.98,1910.44 5204.81,1911.6 5202.45,1912.32 5200,1912.56 5062.56,1912.56 5062.56,4894.8 5308.88,5141.12 5508.88,5341.12 5510.44,5343.02 5511.6,5345.19 5512.32,5347.55 5512.56,5350 5512.56,5974.92 5687.44,5974.92
NN18 on PWR2 (split plane): 5107.44,1380 5107.68,1377.55 5108.4,1375.19 5109.56,1373.02 5111.12,1371.12 5151.12,1331.12 5153.02,1329.56 5155.19,1328.4 5157.55,1327.68 5160,1327.44 5337.44,1327.44 5337.44,112.56 5062.56,112.56 5062.56,1180 5062.32,1182.45 5061.6,1184.81 5060.44,1186.98 5058.88,1188.88 4978.88,1268.88 4976.98,1270.44 4974.81,1271.6 4972.45,1272.32 4970,1272.56 4794.98,1272.56 4765.2,1272.56 4672.56,1365.2 4672.56,1454.8 4685.2,1467.44 5107.44,1467.44
PP18 on PWR2 (split plane): 5227.44,1854.8 5227.44,1605.2 5114.8,1492.56 4680,1492.56 4677.55,1492.32 4675.19,1491.6 4673.02,1490.44 4671.12,1488.88 4651.12,1468.88 4649.56,1466.98 4648.4,1464.81 4647.68,1462.45 4647.44,1460 4647.44,1360 4647.68,1357.55 4648.4,1355.19 4649.56,1353.02 4651.12,1351.12 4751.12,1251.12 4753.02,1249.56 4755.19,1248.4 4757.55,1247.68 4760,1247.44 4767.68,1247.44 4767.44,1245.02 4767.44,112.56 4527.56,112.56 4527.56,1747.44 4850,1747.44 4852.45,1747.68 4854.81,1748.4 4856.98,1749.56 4858.88,1751.12 4995.2,1887.44 5194.8,1887.44
GND on PWR2 (split plane): 5037.44,1174.8 5037.44,112.56 4792.56,112.56 4792.56,1239.82 4800.18,1247.44 4964.8,1247.44
+18 on PWR2 (split plane): 4837.44,8244.8 4837.44,7700 4837.68,7697.55 4838.4,7695.19 4839.56,7693.02 4841.12,7691.12 5287.44,7244.8 5287.44,6125.08 5112.56,6125.08 5112.56,7100 5112.32,7102.45 5111.6,7104.81 5110.44,7106.98 5108.88,7108.88 4262.56,7955.2 4262.56,8287.44 4794.8,8287.44
-24 on PWR2 (split plane): 5437.44,8694.8 5437.44,8250 5437.44,8000 5437.68,7997.55 5438.4,7995.19 5439.56,7993.02 5441.12,7991.12 5887.44,7544.8 5887.44,6125.08 5687.56,6125.08 5687.56,7250 5687.32,7252.45 5686.6,7254.81 5685.44,7256.98 5683.88,7258.88 5162.56,7780.2 5162.56,8250 5162.56,8400 5162.32,8402.45 5161.6,8404.81 5160.44,8406.98 5158.88,8408.88 4998.88,8568.88 4996.98,8570.44 4994.81,8571.6 4992.45,8572.32 4990,8572.56 2760,8572.56 2757.55,8572.32 2755.19,8571.6 2753.02,8570.44 2751.12,8568.88 2441.12,8258.88 2439.56,8256.98 2438.4,8254.81 2437.68,8252.45 2437.44,8250 2437.44,8005.2 2394.8,7962.56 2162.56,7962.56 2162.56,8494.8 2455.2,8787.44 5344.8,8787.44
+24 on PWR2 (split plane): 4237.44,7950 4237.68,7947.55 4238.4,7945.19 4239.56,7943.02 4241.12,7941.12 5087.44,7094.8 5087.44,6125.08 4912.56,6125.08 4912.56,6950 4912.32,6952.45 4911.6,6954.81 4910.44,6956.98 4908.88,6958.88 4158.88,7708.88 3962.56,7905.2 3962.56,8244.8 4005.2,8287.44 4237.44,8287.44
-15 on PWR2 (split plane): 1819.8,8617.56 1080,8617.56 1077.55,8617.32 1075.19,8616.6 1073.02,8615.44 1071.12,8613.88 666.12,8208.88 664.56,8206.98 663.4,8204.81 662.68,8202.45 662.44,8200 662.44,7925 662.68,7922.55 663.4,7920.19 664.56,7918.02 666.12,7916.12 691.12,7891.12 693.02,7889.56 695.19,7888.4 697.55,7887.68 700,7887.44 900,7887.44 902.45,7887.68 904.81,7888.4 906.98,7889.56 908.88,7891.12 933.88,7916.12 935.44,7918.02 936.6,7920.19 937.32,7922.55 937.56,7925 937.56,8119.8 1155.2,8337.44 1919.68,8337.44 1841.12,8258.88 1839.56,8256.98 1838.4,8254.81 1837.68,8252.45 1837.44,8250 1837.44,7750 1837.68,7747.55 1838.4,7745.19 1839.56,7743.02 1841.12,7741.12 1941.12,7641.12 1943.02,7639.56 1945.19,7638.4 1947.55,7637.68 1950,7637.44 2500,7637.44 2502.45,7637.68 2504.81,7638.4 2506.98,7639.56 2508.88,7641.12 2805.2,7937.44 3594.8,7937.44 4687.44,6844.8 4687.44,6125.08 20.1,6125.08 20.1,9079.9 2282.14,9079.9
+24AMP on PWR2 (split plane): 3941.12,8258.88 3939.56,8256.98 3938.4,8254.81 3937.68,8252.45 3937.44,8250 3937.44,7900 3937.68,7897.55 3938.4,7895.19 3939.56,7893.02 3941.12,7891.12 4141.12,7691.12 4887.44,6944.8 4887.44,6125.08 4712.56,6125.08 4712.56,6850 4712.32,6852.45 4711.6,6854.81 4710.44,6856.98 4708.88,6858.88 3608.88,7958.88 3606.98,7960.44 3604.81,7961.6 3602.45,7962.32 3600,7962.56 2812.56,7962.56 2812.56,8194.8 2905.2,8287.44 3969.68,8287.44
-18 on PWR2 (split plane): 5137.44,8394.8 5137.44,8250 5137.44,7775 5137.68,7772.55 5138.4,7770.19 5139.56,7768.02 5141.12,7766.12 5662.44,7244.8 5662.44,6125.08 5512.56,6125.08 5512.56,7050 5512.32,7052.45 5511.6,7054.81 5510.44,7056.98 5508.88,7058.88 4862.56,7705.2 4862.56,8250 4862.32,8252.45 4861.6,8254.81 4860.44,8256.98 4858.88,8258.88 4808.88,8308.88 4806.98,8310.44 4804.81,8311.6 4802.45,8312.32 4800,8312.56 2900,8312.56 2897.55,8312.32 2895.19,8311.6 2893.02,8310.44 2891.12,8308.88 2791.12,8208.88 2789.56,8206.98 2788.4,8204.81 2787.68,8202.45 2787.44,8200 2787.44,7955.2 2494.8,7662.56 1955.2,7662.56 1862.56,7755.2 1862.56,8244.8 1955.2,8337.44 2137.44,8337.44 2137.44,7950 2137.68,7947.55 2138.4,7945.19 2139.56,7943.02 2141.12,7941.12 2143.02,7939.56 2145.19,7938.4 2147.55,7937.68 2150,7937.44 2400,7937.44 2402.45,7937.68 2404.81,7938.4 2406.98,7939.56 2408.88,7941.12 2458.88,7991.12 2460.44,7993.02 2461.6,7995.19 2462.32,7997.55 2462.56,8000 2462.56,8244.8 2765.2,8547.44 4984.8,8547.44
-5 on PWR2 (split plane): 5487.44,9000 5487.68,8997.55 5488.4,8995.19 5489.56,8993.02 5491.12,8991.12 5662.44,8819.8 5662.44,8085 5662.68,8082.55 5663.4,8080.19 5664.56,8078.02 5666.12,8076.12 6087.44,7654.8 6087.44,6125.08 5912.56,6125.08 5912.56,7550 5912.32,7552.45 5911.6,7554.81 5910.44,7556.98 5908.88,7558.88 5462.56,8005.2 5462.56,8250 5462.56,8700 5462.32,8702.45 5461.6,8704.81 5460.44,8706.98 5458.88,8708.88 5358.88,8808.88 5356.98,8810.44 5354.81,8811.6 5352.45,8812.32 5350,8812.56 2450,8812.56 2447.55,8812.32 2445.19,8811.6 2443.02,8810.44 2441.12,8808.88 2141.12,8508.88 2139.56,8506.98 2138.4,8504.81 2137.68,8502.45 2137.44,8500 2137.44,8362.56 1150,8362.56 1147.55,8362.32 1145.19,8361.6 1143.02,8360.44 1141.12,8358.88 916.12,8133.88 914.56,8131.98 913.4,8129.81 912.68,8127.45 912.44,8125 912.44,7930.2 894.8,7912.56 705.2,7912.56 687.56,7930.2 687.56,8194.8 1085.2,8592.44 1825,8592.44 1827.45,8592.68 1829.81,8593.4 1831.98,8594.56 1833.88,8596.12 2317.67,9079.9 5487.44,9079.9
N15 on PWR2 (split plane): 6379.9,20.1 20.1,20.1 20.1,5974.92 4687.44,5974.92 4687.44,5705.2 3644.8,4662.56 3325,4662.56 3322.55,4662.32 3320.19,4661.6 3318.02,4660.44 3316.12,4658.88 3166.12,4508.88 3164.56,4506.98 3163.4,4504.81 3162.68,4502.45 3162.44,4500 3162.44,4350 3162.68,4347.55 3163.4,4345.19 3164.56,4343.02 3166.12,4341.12 3216.12,4291.12 3218.02,4289.56 3220.19,4288.4 3222.55,4287.68 3225,4287.44 3350,4287.44 3352.45,4287.68 3354.81,4288.4 3356.98,4289.56 3358.88,4291.12 3580.2,4512.44 3700,4512.44 3702.45,4512.68 3704.81,4513.4 3706.98,4514.56 3708.88,4516.12 4155.2,4962.44 4237.44,4962.44 4237.44,4680.2 4216.12,4658.88 4214.56,4656.98 4213.4,4654.81 4212.68,4652.45 4212.44,4650 4212.44,1362.5 4212.68,1360.05 4213.4,1357.69 4214.56,1355.52 4216.12,1353.62 4237.44,1332.3 4237.44,100 4237.68,97.55 4238.4,95.19 4239.56,93.02 4241.12,91.12 4243.02,89.56 4245.19,88.4 4247.55,87.68 4250,87.44 5650,87.44 5652.45,87.68 5654.81,88.4 5656.98,89.56 5658.88,91.12 5660.44,93.02 5661.6,95.19 5662.32,97.55 5662.56,100 5662.56,4994.8 5908.88,5241.12 5910.44,5243.02 5911.6,5245.19 5912.32,5247.55 5912.56,5250 5912.56,5974.92 6379.9,5974.92
P24AMP on PWR2 (split plane): 4887.44,5705.2 4241.12,5058.88 4239.56,5056.98 4238.4,5054.81 4237.68,5052.45 4237.44,5050 4237.44,4987.56 4150,4987.56 4147.55,4987.32 4145.19,4986.6 4143.02,4985.44 4141.12,4983.88 3694.8,4537.56 3575,4537.56 3572.55,4537.32 3570.19,4536.6 3568.02,4535.44 3566.12,4533.88 3344.8,4312.56 3230.2,4312.56 3187.56,4355.2 3187.56,4494.8 3330.2,4637.44 3650,4637.44 3652.45,4637.68 3654.81,4638.4 3656.98,4639.56 3658.88,4641.12 4708.88,5691.12 4710.44,5693.02 4711.6,5695.19 4712.32,5697.55 4712.56,5700 4712.56,5974.92 4887.44,5974.92
P24 on PWR2 (split plane): 5087.44,5555.2 4506.12,4973.88 4504.56,4971.98 4503.4,4969.81 4502.68,4967.45 4502.44,4965 4502.44,112.56 4262.56,112.56 4262.56,1337.5 4262.32,1339.95 4261.6,1342.31 4260.44,1344.48 4258.88,1346.38 4237.56,1367.7 4237.56,4644.8 4258.88,4666.12 4260.44,4668.02 4261.6,4670.19 4262.32,4672.55 4262.56,4675 4262.56,5044.8 4908.88,5691.12 4910.44,5693.02 4911.6,5695.19 4912.32,5697.55 4912.56,5700 4912.56,5974.92 5087.44,5974.92
PGND on GND2 (split plane): 6379.9,6125.08 20.1,6125.08 20.1,9079.9 6379.9,9079.9
GND on GND2 (split plane): 6379.9,20.1 20.1,20.1 20.1,5974.92 6379.9,5974.92

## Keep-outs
Keep-Out Layer:
  lines w10: 25,50 6375,50 6375,1200 6350,1200 6350,5950 60,5950 60,1200 25,1200 25,50 ; 25,7900 25,9050 6375,9050 6375,7900 6350,7900 6350,6150 60,6150 60,7900 25,7900

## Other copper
Top Layer:
  rectangle net PGND: 3500,6600 6000,7730
  rectangle net PGND: 500,6600 3000,7730
GND1 (plane layer: these items are gaps in the copper):
  lines w50: 0,6000 6400,6000 ; 0,6100 6400,6100
GND2 (plane layer: these items are gaps in the copper):
  lines w50: 0,6000 6400,6000 ; 0,6100 6400,6100
PWR1 (plane layer: these items are gaps in the copper):
  lines w25: 0,8250 1750,8250 1850,8150 1850,7900 1900,7850 2150,7850 ; 2150,9100 2150,7850 ; 2800,9100 2800,8250 ; 4250,9100 4250,8275 4250,7850 ; 6400,8250 4650,8250 4550,8150 4550,7900 4500,7850 4250,7850 ; 2150,7850 2400,7850 2450,7900 2450,8150 2550,8250 2800,8250 ; 2800,8250 3850,8250 3950,8150 3950,7900 4000,7850 4250,7850
  lines w50: 0,6000 6400,6000 ; 0,6100 6400,6100
PWR2 (plane layer: these items are gaps in the copper):
  lines w25: 2150,8350 1950,8350 ; 2322.5,9102.5 1825,8605 1080,8605 675,8200 675,7925 700,7900 900,7900 925,7925 925,8125 1150,8350 1950,8350 ; 4250,4975 4150,4975 3700,4525 3575,4525 3350,4300 3225,4300 3175,4350 3175,4500 3325,4650 3650,4650 4700,5700 4700,6000 ; 4250,6100 4900,6100 4900,6950 4150,7700 3950,7900 3950,8250 4000,8300 4250,8300 ; 4500,8300 4250,8300 ; 4515,1760 4850,1760 ; 4550,100 4250,100 4250,1337.5 4225,1362.5 4225,4650 4250,4675 4250,5050 4900,5700 4900,6000 ; 4550,6100 5100,6100 5100,7100 4250,7950 4250,8300 ; 4700,6100 4700,6850 3600,7950 2800,7950 ; 4794.98,1260 4780,1245.02 4780,100 5050,100 ; 4815,100 4515,100 4515,4965 5100,5550 5100,6000 ; 4850,4900 5050,4900 ; 4850,6100 5300,6100 5300,7250 ; 5300,6000 5300,5450 4850,5000 4850,1760 ; 5350,1340 5160,1340 5120,1380 5120,1480 ; 5500,6000 5500,5350 5300,5150 5050,4900 ; 5500,6100 5500,7050 4850,7700 4850,8250 4800,8300 3450,8300 2900,8300 2800,8200 2800,7950 ; 5500,9100 5500,9000 5675,8825 5675,8085 6100,7660 6100,6100 5840,6100 ; 5650,6100 5900,6100 5900,7550 5450,8000 5450,8250 5450,8700 5350,8800 2450,8800 2150,8500 2150,7950 2400,7950 2450,8000 2450,8250 2760,8560 4990,8560 5150,8400 5150,8250 5150,7775 5675,7250 5675,6100 ; 5700,6000 5700,5300 5512.56,5112.56 5350,4950 5350,100 ; 5900,6000 5900,5250 5650,5000 5650,100 5350,100 ; 1950,8350 1850,8250 1850,7750 1950,7650 2500,7650 2800,7950 ; 4850,1760 4990,1900 5050,1900 ; 5050,100 5350,100 ; 5050,100 5050,1180 4970,1260 4760,1260 4660,1360 4660,1460 4680,1480 5120,1480 ; 5050,1900 5200,1900 5240,1860 5240,1600 5120,1480 ; 5050,1900 5050,4900
  lines w50: 0,6000 6400,6000 ; 0,6100 6400,6100

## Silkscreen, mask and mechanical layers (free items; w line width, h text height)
Top Overlay:
  rectangle: 2010,4615 3510,4980
  lines w10: 1900,6210 ccw(c2002.5,6307.5) 2102.56,6207.5 ; 2102.6,6207.47 ccw(c2200,6310) 2300,6210 ; 2500,7985 ccw(c2602.5,8082.5) 2702.56,7982.5 ; 2702.6,7982.47 ccw(c2800,8085) 2900,7985 ; 3000,7985 ccw(c3102.5,8082.5) 3202.56,7982.5 ; 3202.6,7982.47 ccw(c3300,8085) 3400,7985 ; 3500,7985 ccw(c3602.5,8082.5) 3702.56,7982.5 ; 3702.6,7982.47 ccw(c3800,8085) 3900,7985
  lines w15: 150,1430 250,1430 ; 170,1400 230,1400 ; 190,1370 210,1370 ; 200,1430 200,1505 ; 450,7930 550,7930 ; 470,7900 530,7900 ; 490,7870 510,7870 ; 500,7930 500,8005 ; 2330,6340 2430,6340 ; 2350,6310 2410,6310 ; 2370,6280 2390,6280 ; 2380,6340 2380,6415 ; 2750,7815 2850,7815 ; 2770,7785 2830,7785 ; 2790,7755 2810,7755 ; 2800,7815 2800,7890 ; 3250,7815 3350,7815 ; 3270,7785 3330,7785 ; 3290,7755 3310,7755 ; 3300,7815 3300,7890 ; 3750,7815 3850,7815 ; 3770,7785 3830,7785 ; 3790,7755 3810,7755 ; 3800,7815 3800,7890 ; 6200,4955 6300,4955 ; 6220,4925 6280,4925 ; 6240,4895 6260,4895 ; 6250,4955 6250,5030
  text "-5V" at 700,7940 h45
  text "-15V" at 980,7940 h45
  text "-21V" at 1280,7940 h45
  text "-10V" at 1580,7940 h45
  text "-18V" at 1880,7940 h45
  text "-24V" at 2180,7940 h45
  text "+24V" at 3980,7940 h45
  text "+18V" at 4280,7940 h45
  text "+10V" at 4580,7940 h45
  text "24AMP" at 4880,7940 h45
  text "+21V" at 5180,7940 h45
  text "+15V" at 5480,7940 h45
  text "+5V" at 5800,7940 h45
  text "+15V" at 2480,7825 h45
  text "+15V" at 2980,7825 h45
  text "+24AMP" at 3450,7825 h45
  text "+15V" at 1700,6325 h45
  text "EOM Driver Power" at 4050,5290 h240
  text "D0900848" at 1230,4775 h180
  text "rev. C" at 1590,4615 h160
Bottom Overlay:
  lines w10: 2160,5020 2160,5470 2440,5470 2440,5020 2160,5020
  text "B5" at 2120,5020 h45
Top Solder:
  rectangle: 495,6595 3005,7735
  rectangle: 3495,6595 6005,7735
Mechanical 1:
  the board outline again, w10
